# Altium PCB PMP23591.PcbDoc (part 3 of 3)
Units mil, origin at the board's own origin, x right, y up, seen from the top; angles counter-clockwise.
Board outline 3937.01 x 3937.01 mil, 6 copper layers (Top Layer, GND, Power Layer, Signal Layer, GND (Mid4), Bottom Layer), stack 66.824 mil thick; 197 components, 79 nets, 496 pads, 588 vias.
Unrouted connection lines stored in the file: 309.
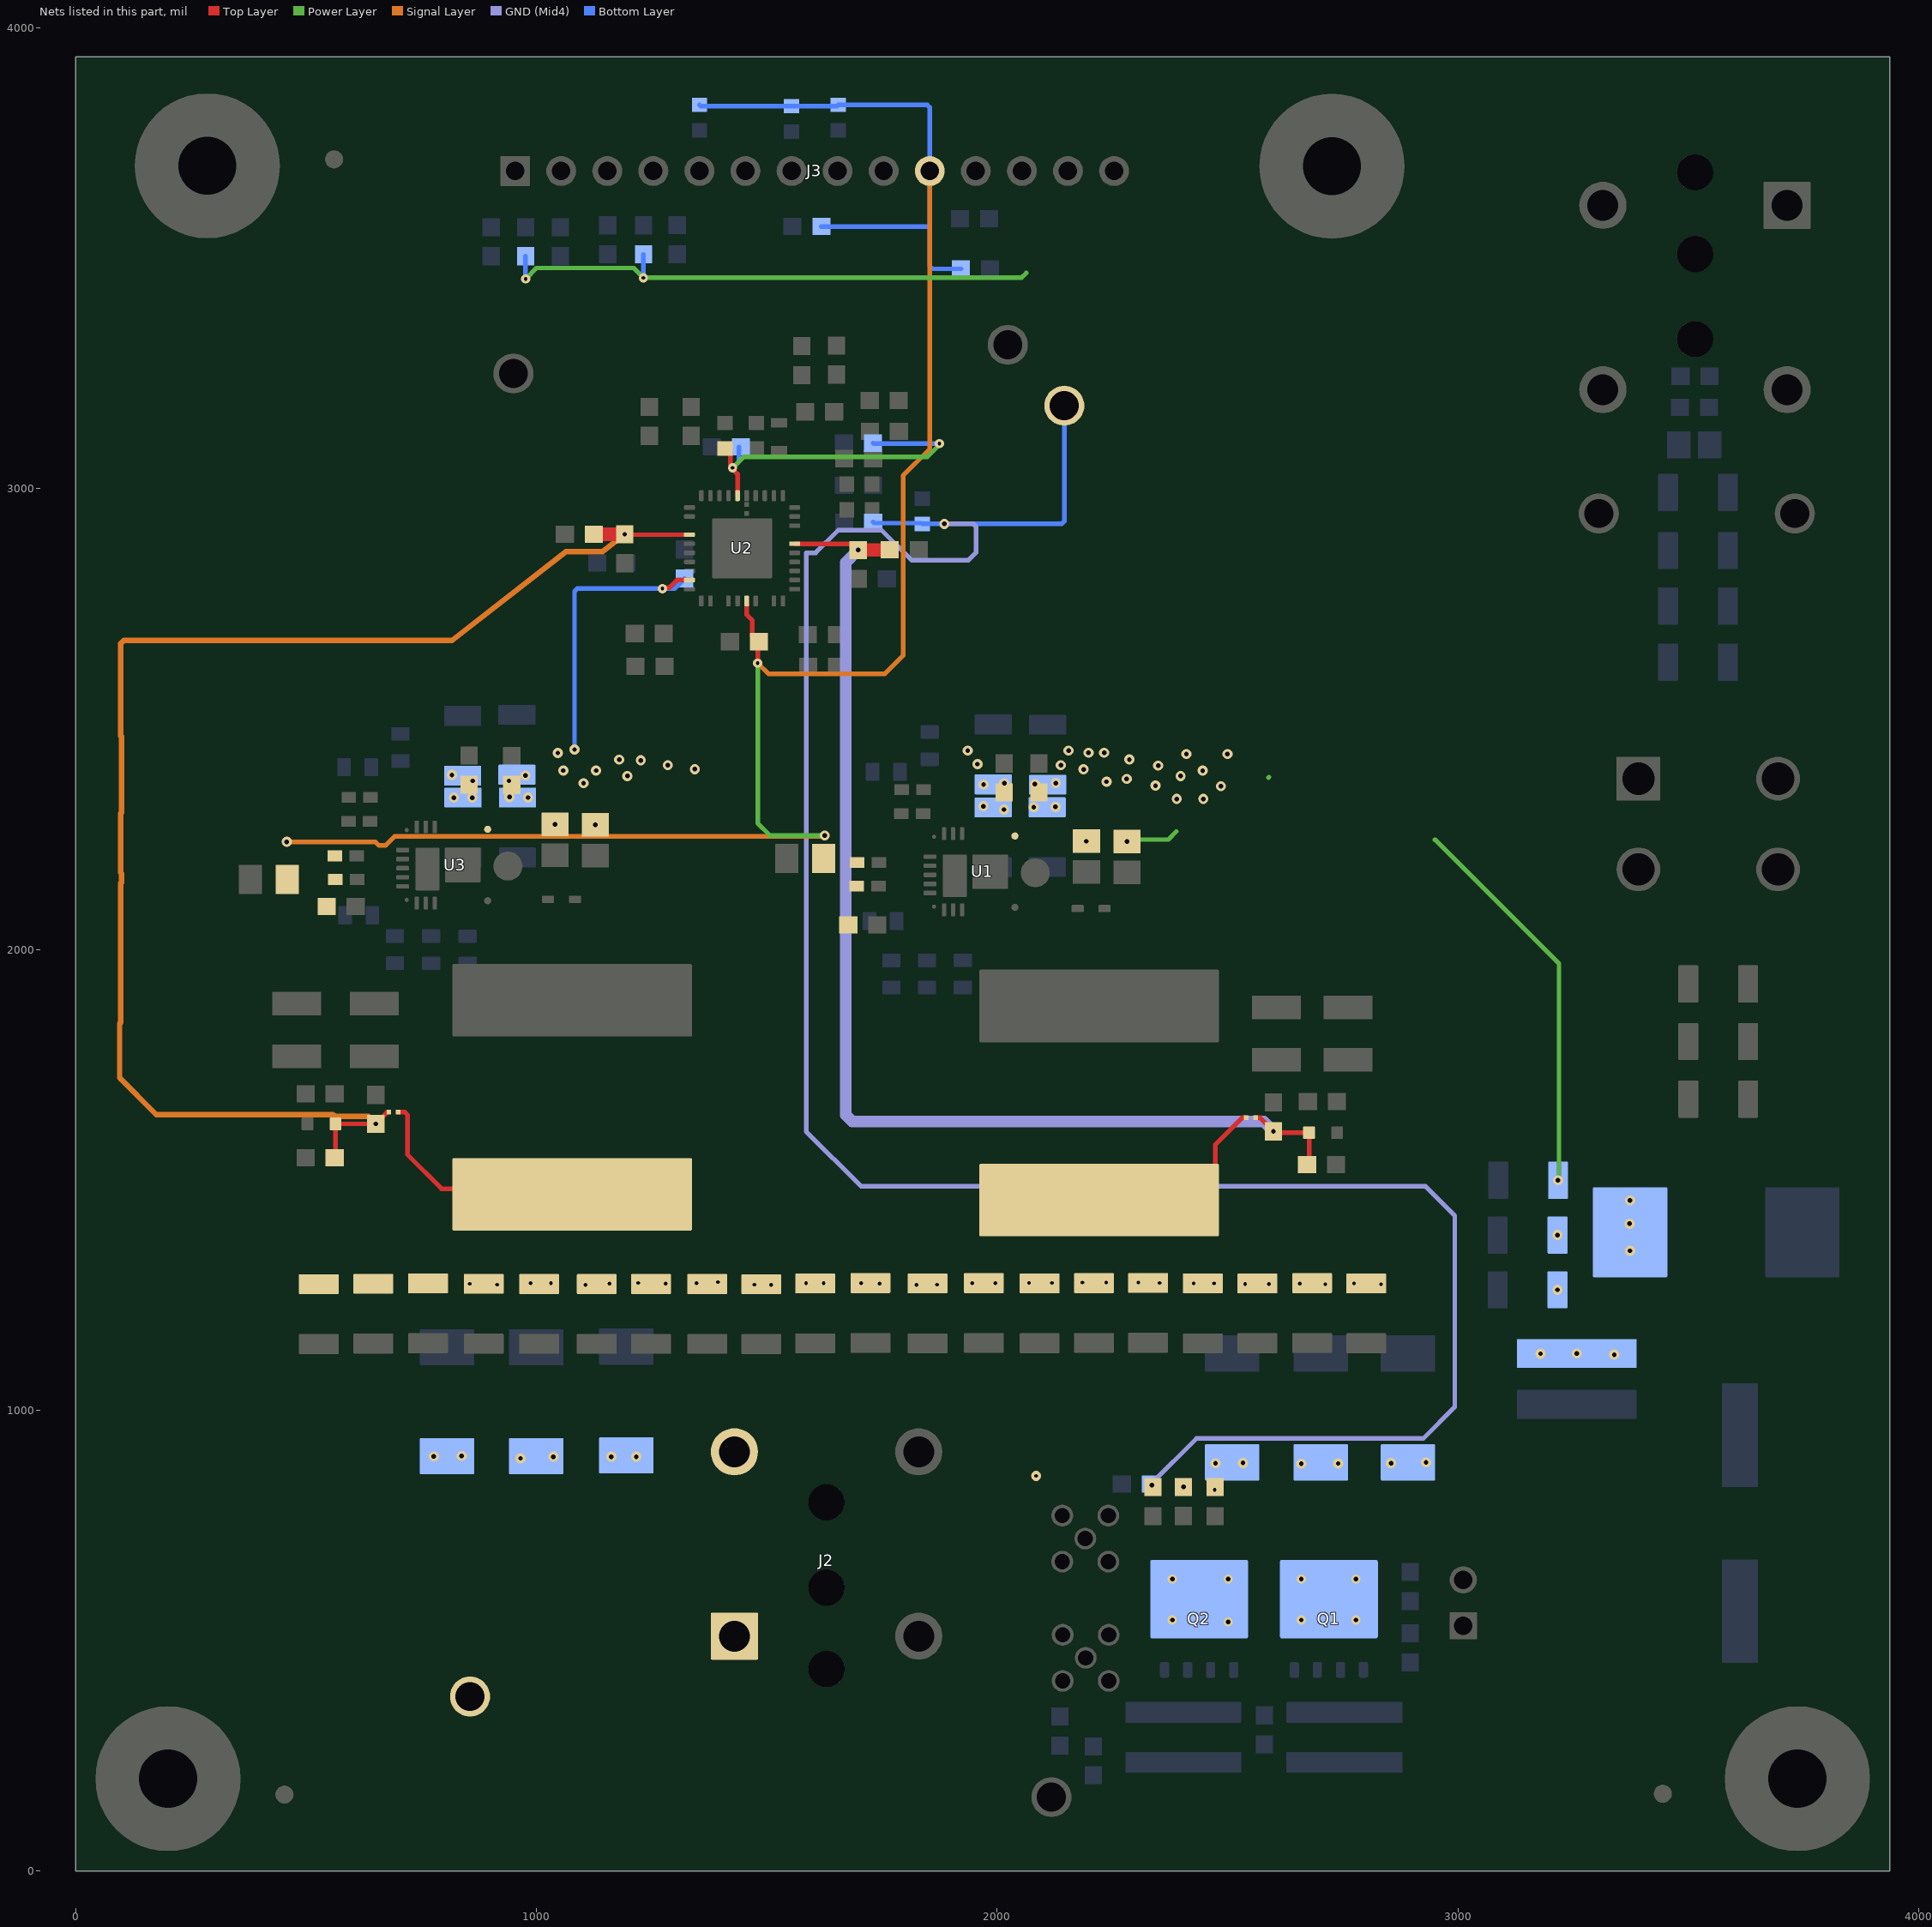
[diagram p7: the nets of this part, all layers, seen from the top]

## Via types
v1: diameter 22, hole 10, Top Layer to Bottom Layer, tented both sides, 256 vias
v2: diameter 20, hole 10, Top Layer to Bottom Layer, tented both sides, 193 vias
v3: diameter 22, hole 8, Top Layer to Bottom Layer, tented both sides, 59 vias
v4: diameter 20, hole 8, Top Layer to Bottom Layer, tented both sides, 56 vias
v5: diameter 19.68, hole 7.87, Top Layer to Bottom Layer, tented both sides, 18 vias
v6: diameter 230, hole 125, Top Layer to Bottom Layer, 4 vias
v7: diameter 24, hole 8, Top Layer to Bottom Layer, tented both sides, 2 vias

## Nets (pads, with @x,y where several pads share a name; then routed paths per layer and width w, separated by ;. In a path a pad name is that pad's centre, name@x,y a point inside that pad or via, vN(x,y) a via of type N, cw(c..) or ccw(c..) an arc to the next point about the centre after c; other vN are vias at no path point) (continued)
VCC: C22.1 C23.1 C40.1 C53.1 C54.1 J3.10 R2.1 R15.2 R21.1 R39.2 R41.2 R42.2 R43.2 R64.1 R65.1 U2.14 | length 4400.5
  Top Layer w10: U2.14@1456.05,2756.46 1456.05,2726.64 1468.17,2714.53 1468.17,2678.61 1480.01,2666.77 v4(1480.01,2621.39)
  Power Layer w10: v4(1480.01,2621.39) 1480.01,2274 1506.76,2247.26 v1(1625.53,2247.26)
  Signal Layer w10: v1(457.68,2233.61) 649.96,2233.61 658.03,2225.54 672.01,2225.54 692.1,2245.63 1623.9,2245.63 v1(1625.53,2247.26) ; v4(1480.01,2621.39) 1503.06,2598.34 1756.3,2598.34 1795.76,2637.8 1795.76,3028.58 1853.51,3086.34 J3.10@1853.51,3689.57
  Bottom Layer w10: R41.2@1353.76,3833.14 1356.57,3830.34 R42.2@1553.51,3830.34 1652.48,3830.34 R43.2@1655.28,3833.14 1847.66,3833.14 1853.51,3827.28 J3.10@1853.51,3689.57 1853.51,3568.98 ; R64.1@1618.31,3568.98 1853.51,3568.98 ; R65.1@1921.16,3477.23 1859.37,3477.23 1853.51,3483.09 1853.51,3568.98
VDDA: C41.2 R28.1 R46.2 U2.32 | length 782.3
  Top Layer w10: C41.2@1408.98,3087.48 1409.97,3087.48 1420.72,3076.74 1420.72,3052.78 1425.57,3047.92 v4(1425.57,3045.22) 1425.57,3042.51 1436.37,3031.71 U2.32@1436.37,2984.81
  Power Layer w10: v4(1425.57,3045.22) 1449.15,3068.79 1847.99,3068.79 1874.33,3095.13 v4(1874.33,3097.84)
  Bottom Layer w10: v4(1425.57,3045.22) 1439.55,3059.19 R28.1@1439.55,3090.75 ; R46.2@1730.43,3098.93 1731.72,3097.64 v4@1874.14,3097.64
VIN: C9.2 C10.2 C11.2 C18.2 C19.2 C20.2 C21.2 C24.2 C25.2 C26.1 C27.1 C39.1 C45.2 C46.2 C47.2 C48.2 C49.2 C50.2 C51.1 C52.1 L1.2 R1.2 R40.2 R60.2 U1.7 U2.8 U3.7 | length 2851.1
  Top Layer w10: v4(1273.19,2783.08) 1275.1,2784.99 1288.48,2784.99 1305.23,2801.74 U2.8@1332.04,2801.74
  Power Layer w10: v4(976.22,3455.2) 1000,3478.98 1146.6,3478.98 ; 1146.63,3479.01 1165.58,3479.01 1210.7,3478.98 v4(1231.9,3457.77) 2052.51,3457.77 2062.93,3468.19 ; 2269.63,2238.49 2371.23,2238.49 2388.77,2256.03 ; 2588.87,2372.93 2590.31,2374.37 ; 2950.23,2238.15 3219.3,1969.08 3219.3,1500.7 v1(3217.39,1498.79)
  Bottom Layer w10: v4(976.22,3455.2) R40.2@976.22,3504.77 ; v1(1082.55,2433.83) 1082.55,2777.22 1088.41,2783.08 v4(1273.19,2783.08) 1299.2,2783.08 1306.54,2790.41 1307.52,2790.41 1321.22,2804.11 C39.1@1321.22,2805.1 ; v4(1231.9,3457.77) 1231.9,3508.25 R60.2@1232.32,3508.66
  other v1: 3339.38,1120.39 3179.38,1122.5 3257.87,1122.97 3216.21,1261.25 3373.71,1345.83 3216.21,1380 3372.73,1404.74 3373.71,1455.17 2281.63,2234.15 2193.58,2234.77 1040.14,2271.36 1127.74,2270.51 2014.62,2303.64 2079.33,2308.59 2126.52,2309.42 1970.04,2310.85 2389.62,2326.6 2447.48,2326.6 820.58,2329.42 860.58,2329.42 981.48,2329.58 941.19,2330.68 2485.58,2354.29 2343.62,2355.49 1970.45,2357.94 2081.78,2358.7 1102.07,2360.78 2015.19,2360.78 2127.09,2361.07 2237.31,2364.05 861.21,2366 940.16,2365.99 2281.1,2370.18 1197.15,2376.45 2398.11,2376.45 975.91,2377.49 816.4,2378.74 1058.1,2388.24 1129.15,2388.24 2445.96,2388 1343.37,2391.34 2187.39,2390.88 2349.41,2398.98 1284.84,2399.98 2138.06,2399.98 1957.09,2402.16 1226.32,2410.35 1179.49,2411.88 2286.75,2412.31 2410.7,2424.09 2499.76,2424.09 1046.2,2426.33 2198.24,2426.75 2232.05,2426.75 1935.95,2431.66 2154.93,2431.66
Vout: C29.2 C30.2 C31.2 C32.2 C33.2 C34.2 C35.2 C36.2 C57.1 C58.2 C59.2 C60.2 C61.2 C62.2 C63.2 C64.2 C65.2 C66.2 C67.2 C72.2 C73.2 C74.2 C76.2 C79.2 C80.2 C81.2 C82.2 C83.2 C84.2 J2.1 L4.2 L6.2 NT1.2 NT2.2 Q1.5 Q1.6 Q1.7 Q1.8 Q1.9@2719.98,589.79 Q2.5 Q2.6 Q2.7 Q2.8 Q2.9@2438.28,589.69 R18.2 R37.2 R56.2 VOUT_BODE.1 VOUT_PWR1.1 | length 5920.5
  Top Layer w10: NT2.2@699.36,1646.64 714.14,1646.64 720,1640.78 720,1554.3 793.74,1480.56 L6.2@972.48,1480.56 ; L4.2@2221.16,1455.96 2399.9,1455.96 2473.64,1529.7 2473.64,1576.61 2531.71,1634.67 NT1.2@2540.58,1634.67
  GND (Mid4) w10: v1(1885.22,2923.63) 1948.01,2923.63 1953.87,2917.77 1953.87,2860.97 1937.88,2844.97 1813.92,2844.97 1748.97,2909.91 1654.89,2909.91 1605.77,2860.79 1585.36,2860.79 1585.36,1604.83 1704.12,1486.08 2929.22,1486.08 2993.24,1422.06 2993.24,1006.86 2924.83,938.45 2432.43,938.45 2335.53,841.55 2335.53,833.26 v2@2335.92,832.87
  Bottom Layer w10: R18.2@1730.69,2927.38 1732.75,2925.32 R37.2@1834.9,2925.32 ; R37.2@1836.84,2923.39 1837.08,2923.63 v1(1885.22,2923.63) 2139.72,2923.63 2145.57,2929.49 VOUT_BODE.1@2145.57,3180.17
  other v1: 2404.43,833.33 2660.11,883.81 2740.1,884.21 2473.78,884.58 2533.35,885.41 2854.79,885 2930.82,886.58 965.29,895.37 1036.58,898.95 1162.27,898.95 1216.49,898.95 777.03,899.67 837.45,900.59
  other v2: 2501.39,540.47 2380,544.45 2660,544.45 2778.89,544.45 2380,633.5 2501.39,633.5 2660,633.5 2778.89,633.5 2335.53,837.4
  other v3: 2472.16,827.06 2084.33,857.27 914.5,1272.42 1106.04,1271.9 1472.63,1272.42 1509.46,1271.9 1824.51,1271.9 1869.5,1272.42 2712.02,1273.4 2833.12,1273.4 854.74,1274.05 2538.07,1273.77 2589.52,1273.77 986.98,1275.45 1031.45,1275.45 1158.1,1274.86 1280.41,1274.86 1347.08,1275.32 1584.94,1275.32 1623.03,1275.32 1704.42,1275.32 1744.56,1274.86 2426.59,1274.94 2470.51,1274.94 2656.87,1274.74 2774.48,1274.94 1220.66,1276 1945.55,1275.73 1995.95,1275.73 2068.98,1276 2118.69,1276 2352.53,1276.1 2185.04,1276.97 2236.68,1276.97 2306.19,1277.17 1393.66,1278.08
VOUT1: C37.1 C43.1 C77.2 NT1.1 R9.2 R13.2 U2.23 | length 2590.3
  Top Layer w10: U2.23@1560.38,2880.48 1684.53,2880.48 v1(1698.06,2866.95) ; NT1.1@2560.58,1634.67 2570.95,1634.67 2599.45,1606.16 v1(2599.45,1605.18) ; C37.1@2602.45,1602.18 R9.2@2676.9,1602.18 2676.9,1537.33 R13.2@2672.63,1533.06
  Top Layer w30: v1(1698.06,2866.95) C77.2@1766.84,2867.84
  GND (Mid4) w25: v1(1698.06,2866.95) 1670.86,2839.75 1670.86,1782.86 1671.38,1782.34 1671.38,1756.35 1670.86,1755.83 1670.86,1640.82 1685.5,1626.18 2578.45,1626.18 v1(2599.45,1605.18)
VOUT2: C68.1 C69.1 C78.2 NT2.1 R33.2 R36.2 U2.3 | length 3127.7
  Top Layer w10: R36.2@561.72,1547.45 563.8,1549.53 R33.2@563.8,1621.33 v1(651.15,1621.3) ; v1(651.15,1621.3) 651.15,1622.28 675.5,1646.64 NT2.1@679.36,1646.64 ; v1(1191.39,2901.15) 1192.38,2900.16 U2.3@1332.04,2900.16
  Top Layer w30: C78.2@1124.6,2901.15 v1(1191.39,2901.15)
  Signal Layer w12: v1(651.15,1621.3) 634.89,1637.55 571.24,1637.55 566.29,1637.55 558.42,1641.5 174.8,1641.5 95,1721.3 95,1839.06 97.69,1841.75 97.69,2143.71 98.87,2144.9 98.87,2164.68 97.69,2165.87 97.69,2295.33 98.87,2296.51 98.87,2462.23 97.69,2463.41 97.69,2664.1 104.71,2671.13 817.09,2671.13 1063.56,2863.29 1138.7,2863.29 1142.72,2863.29 1146.08,2865.83 v1(1191.39,2901.15)
pads on no net: FID1.1 FID2.1 FID3.1 H1.1 H2.1 H3.1 H4.1 H5.0 H6.0 H7.0 H8.0 J1. J2. LBL1.0 Q1.9@2626.58,514.6 Q1.9@2667.62,526.21 Q1.9@2667.62,571.49 Q1.9@2667.62,616.76 Q1.9@2719.98,526.21 Q1.9@2719.98,571.49 Q1.9@2719.98,576.8 Q1.9@2719.98,616.76 Q1.9@2772.35,526.21 Q1.9@2772.35,571.49 Q1.9@2772.35,616.76 Q1.9@2813.39,514.6 Q2.9@2344.88,514.49 Q2.9@2385.92,526.11 Q2.9@2385.92,571.38 Q2.9@2385.92,616.66 Q2.9@2438.28,526.11 Q2.9@2438.28,571.38 Q2.9@2438.28,576.7 Q2.9@2438.28,616.66 Q2.9@2490.64,526.11 Q2.9@2490.64,571.38 Q2.9@2490.64,616.66 Q2.9@2531.69,514.49 U2.5

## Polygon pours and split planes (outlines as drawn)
NetC68_2 on Top Layer "TOP_LAYER_NETC68_2_P599" (solid, remove dead copper, pour order 599): 691.4,1822.76 691.31,1822.86 408.06,1822.86 408.06,1735.65 423.32,1720.38 527.34,1720.38 527.34,1651.34 715.48,1651.34 715.48,1822.44 715.43,1822.49
NetC37_2 on Top Layer "TOP_LAYER_NETC37_2_P598" (solid, remove dead copper, pour order 598): 2557.04,1807.43 2557.14,1807.53 2840.38,1807.53 2840.38,1720.32 2825.12,1705.06 2706.34,1705.06 2706.34,1636.01 2585.29,1636.01 2532.96,1688.34 2532.96,1807.11 2533.02,1807.17
AGND on Top Layer "TOP_LAYER_AGND" (solid, remove dead copper, pour order 600): 1240.55,2932.63 1159.84,2932.63 1159.84,3359.12 1180.72,3380 1906.22,3380 1906.22,2929.19 1710.71,2929.19 1710.71,3119.78 1705.53,3124.95 1240.55,3124.95
Vout on Top Layer "TOP_LAYER_VOUT_P590" (solid, remove dead copper, pour order 590): 613.53,1574.72 615.4,1572.84 2548.5,1572.84 2548.5,1542.28 2598.11,1492.67 2950.53,1492.67 2950.53,809.15 1760,809.15 1760,119.24 655.76,119.24 433.11,341.89 433.11,1314.89
VIN on Top Layer "TOP_LAYER_VIN_P603" (solid, remove dead copper, pour order 603): 415.12,2557.57 2560.58,2557.57 2560.58,2205.11 1940.94,2205.11 1940.94,2355.49 1943.71,2358.25 1943.71,2367.6 1772.47,2367.6 1772.47,2275.07 1769.51,2272.11 1777.65,2263.97 1837.86,2263.97 1837.86,2248.99 1838.63,2248.22 1835.02,2244.61 1797.4,2244.61 1797.4,2204.21 1796.49,2205.11 1717.6,2205.11 1717.6,2241.38 1583.39,2241.38 415.12,2241.38
NetL4_1 on Top Layer "TOP_LAYER_NETL4_1_P596" (solid, remove dead copper, pour order 596): 2510,1786.85 1954.09,1786.63 1954.09,2104.98 1961.61,2112.5 2146.13,2112.5 2198.24,2060.39 2510,2060.39
VCC on Top Layer "TOP_LAYER_VCC2_P270" (solid, remove dead copper, pour order 591): 415.12,2246.39 584.14,2246.39 584.14,2060.85 544.56,2060.85 434.99,2060.85 414.91,2080.93 414.91,2246.19
VCC on Top Layer "TOP_LAYER_VCC_P593" (solid, remove dead copper, pour order 593): 1584.94,2271.68 1715.57,2271.68 1715.57,2105.14 1715.57,2100.16 1714.59,2093.88 1714.59,2026.27 1605.02,2026.27 1584.94,2046.35
NetL6_1 on Top Layer "TOP_LAYER_NETL6_1_P595" (solid, remove dead copper, pour order 595): 1366.79,1807.33 810.32,1807.33 810.32,2135.62 904.54,2135.62 1058.1,2135.62 1058.1,2050.61 1366.79,2055.06
+Filter on Top Layer "TOP_LAYER_+FILTER_P601" (solid, remove dead copper, pour order 601): 3552.96,2241.38 3552.96,1250 3851.29,1250 3907.27,1250 3914.97,1257.7 3913.7,2241.38
PGND on Top Layer "TOP_LAYER_PGND_P604" (solid, remove dead copper, pour order 604): -43.69,7.99 3893.31,7.99 3893.31,2242.99 3028.16,2242.99 3028.16,3944.99 -43.69,3944.99
VIN on Power Layer "POWER_LAYER_VIN_P605" (solid, remove dead copper, pour order 605): 1944.42,2515.13 1942.22,2517.32 1868.99,2517.32 1868.99,2376.82 1882.88,2362.93 1943.71,2362.93 1943.71,2227.2 1962.92,2207.99 2602.44,2207.99 2602.44,1786.85 2886.3,1786.85 2888.45,1789.01 2888.45,1035 3683.79,1035 3683.79,1500.8 3427.7,1500.8 3427.7,2128.78 3122.59,2128.78 3039.33,2212.04 3004.5,2212.04 2968.75,2240.12 2950.23,2278.77 2950.23,3570.39 2043.87,3570.39 2043.87,2594.52 1944.42,2594.52
Vout on Power Layer "POWER_LAYER_VOUT_P606" (solid, remove dead copper, pour order 606): 205.04,1510 205.04,716.82 322.61,716.82 322.61,161.53 1760,161.53 1760,809.15 2290.12,809.15 2290.12,584.67 2809.25,584.67 2809.25,1510
PGND on Power Layer "POWER_LAYER_PGND_P615" (solid, remove dead copper, pour order 615): 20.05,17.74 3957.06,17.74 3957.06,2252.74 3050,2252.74 3050,3954.74 20.05,3954.74
NetC75_2 on Bottom Layer "BOTTOM_LAYER_NETC75_2_P608" (solid, remove dead copper, pour order 608): 2098.08,397.48 2138.2,397.61 2236.33,397.29 2236.33,466.54 2235.35,467.52 2248.25,480.41 2625.28,480.41 2769.3,480.41 2769.3,474.8 2774.91,480.41 2889.82,480.41 2889.82,245.94 2098.08,243.59
VIN on Bottom Layer "TOP_LAYER_VIN_P018" (solid, remove dead copper, pour order 613): 1102.63,2437.41 1102.07,2437.97 1102.07,2469.83 771.08,2469.83 771.08,2237.77 1367.98,2237.77 1367.98,2437.41
HS1 on Bottom Layer "BOTTOM_LAYER_HS1_P592" (solid, remove dead copper, pour order 592): 1873.2,2236.56 1872.67,2236.03 1721.09,2236.03 1721.09,2239.31 1669.1,2291.3 1669.1,2522.56 1900.35,2522.56 1889.88,2512.09 1889.88,2453.83 1876.19,2440.14 1758.7,2440.14 1758.7,2321.43 1781.86,2298.27 1873.17,2298.27 1873.17,2235.41 1873.22,2235.36
HS2 on Bottom Layer "BOTTOM_LAYER_HS2_P594" (solid, remove dead copper, pour order 594): 740.73,2499.61 740.66,2499.55 649.04,2499.55 561.72,2499.55 561.72,2322.76 616.42,2268.05 628.99,2268.05 638.7,2258.35 710.65,2258.35 710.65,2283.73 665.57,2328.81 624.53,2369.85 624.53,2418.04 634.64,2428.15 741.44,2428.15 741.44,2499.74 740.73,2500.45
NetC1_1 on Bottom Layer "BOTTOM_LAYER_NETC1_1_P597" (solid, remove dead copper, pour order 597): 3103.56,1071.59 3104.09,1071.06 3104.09,815.8 3683.79,815.8 3694.52,826.52 3694.52,1074.27 3106.25,1074.27 3103.65,1071.67
Vout on Bottom Layer "BOTTOM_LAYER_VOUT_P610" (solid, remove dead copper, pour order 610): 2991.7,488.74 2196.38,488.74 2196.38,790 1957.95,790 1370,790 1370,204.02 1345.98,180 715,180 715,1031.13 2991.7,1031.13
VIN on Bottom Layer "TOP_LAYER_VIN3_P079" (solid, remove dead copper, pour order 609): 3151.25,1602.33 3151.25,1600.12 3151.25,1598.75 3151.25,1201.31 3105.22,1201.31 3049.45,1145.54 3049.45,1083.39 3542.76,1083.39 3542.76,1602.33
AGND3 on Bottom Layer "BOTTOM_LAYER_AGND3_P611" (solid, remove dead copper, pour order 611): 330,2198.65 330,1920 337.73,1912.27 911.32,1912.27 911.32,1994.46 902.07,2003.71 619.52,2003.71 619.52,2116.9 616.42,2120 691.7,2120 691.7,2172.91 691.7,2180.93 690.7,2181.93 623.22,2181.93 620.72,2184.43 620.72,2198.65
AGND2 on Bottom Layer "BOTTOM_LAYER_AGND2_P612" (solid, remove dead copper, pour order 612): 1693.27,2150.5 1701.25,2150.23 1825.39,2150.23 1825.39,2095.75 1824.27,2094.64 1748.97,2094.64 1748.97,1937.1 1975,1937.1 1975,1870.72 1974.03,1869.75 1693.27,1869.75
PGND on Bottom Layer "BOTTOM_LAYER_PGND_P620" (solid, remove dead copper, pour order 620): 2.73,13.03 3939.73,13.03 3939.73,2248.03 3052.72,2248.03 3052.72,3950.03 2.73,3950.03
VIN on Bottom Layer "TOP_LAYER_VIN_P018" (solid, remove dead copper, pour order 614): 2586.17,2448.18 2586.17,2218.61 1904.25,2218.61 1904.25,2448.18
+Filter on Bottom Layer "BOTTOM_LAYER_+FILTER_P619" (solid, remove dead copper, pour order 619): 3555.13,2242.47 3555.13,1252.63 3915.87,1252.63 3915.87,2242.47
+Vin_Main on Bottom Layer "BOTTOM_LAYER_+VIN_MAIN_P618" (solid, remove dead copper, pour order 618): 3780,3680 3785,3675 3785,2885 3750,2850 3750,2315 3630.52,2315 3542.68,2402.84 3542.68,3002.32 3510,3035 3514.65,3039.65 3514.65,3544.65 3655,3685 3785,3685
GNDin on Bottom Layer "BOTTOM_LAYER_GNDIN_P616" (solid, remove dead copper, pour order 616): 3260,3677.5 3260,2893.36 3251.64,2885 3286.64,2850 3340,2850 3340,2315.1 3350,2305.1 3359.1,2314.21 3456.19,2314.21 3456.19,2364.55 3510,2418.36 3510,3520 3352.5,3677.5
PGND on GND "GND_PGND_P602" (solid, remove dead copper, pour order 602): 0,5 3937.01,5 3937.01,2240 3050,2240 3050,3942 0,3942
VIN on Signal Layer "SIGNAL_LAYER_VIN_P588" (solid, remove dead copper, pour order 588): 996.99,2281.54 996.99,2249.49 1331.15,2249.49 1332.04,2248.61 1336.67,2253.24 1336.67,2281.54 2110.87,2281.54 2181.76,2210.64 2861.22,2210.64 2861.22,2574.16 2826.22,2609.16 2803.77,2586.71 2342.63,2586.71 2342.63,2569.23 2243.62,2470.23 1384.86,2470.23 1236.67,2618.42 718.29,2618.42 718.29,2306.4 972.12,2306.4
Vout on Signal Layer "SIGNAL_LAYER_VOUT_P589" (solid, remove dead copper, pour order 589): 235.8,1470 235.8,716.82 664.24,716.82 664.24,145.71 1707.21,145.71 1707.21,809.15 2306.19,809.15 2306.19,613.5 2802.8,613.5 2802.8,1470
PGND on Signal Layer "SIGNAL_LAYER_PGND_P617" (solid, remove dead copper, pour order 617): 3.46,9 3940.47,9 3940.47,2244 3050,2244 3050,3946 3.46,3946
PGND on GND (Mid4) "GND_PGND_P607" (solid, remove dead copper, pour order 607): 0,5 3937.01,5 3937.01,2240 3050,2240 3050,3942 0,3942

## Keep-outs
Keep-Out Layer:
  text ".Layer_Name" at 577,-858.49 h30

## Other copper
Top Layer:
  pour cut-out: 705.1,1802.02 705.1,1584.13 1349.28,1584.13 1349.28,1802.02
  pour cut-out: 1951.53,1797.3 1951.53,1586.73 2569.03,1586.73 2569.96,1585.8 2569.96,1797.3
  pour cut-out: 1546.83,2779 1537.31,2779 1537.31,2962.26 1547.99,2962.26
  pour cut-out: 1345.19,2963.07 1345.19,2971.49 1441.05,2971.49 1441.05,2962.46
  pour cut-out: 1354.88,2779.33 1345.36,2779.33 1345.36,2963.07 1356.04,2963.07
  pour cut-out: 1451.92,2769.93 1451.92,2778.97 1546.9,2778.97 1546.9,2769.33
  pour cut-out: 1345.19,2769.75 1345.19,2778.97 1422.86,2778.97 1422.86,2769.26
  pour cut-out: 1470.86,2962.69 1470.86,2970.72 1548,2970.72 1548,2962.2
  text ".Layer_Name" at 577,-858.49 h30
Bottom Layer:
  text ".Layer_Name" at 577,-858.49 h30

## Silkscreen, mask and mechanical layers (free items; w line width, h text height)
Top Overlay:
  rectangle: 2980,160 3280,260
  lines w4: 1535.41,3477.07 1535.41,3620.19 ; 1635.35,3478.78 1635.35,3615.78
  lines w5: 900,3050 25,3050 25,2050 1025,2050 ; 2025,2050 3025,2050 3025,3050 2150,3050
  lines w10: 1101.51,2587.02 1102.07,2587.58
  text "PG1" at 1373,3547.09 h30 r90
  text "EN1" at 1069.97,3545.44 h30 r90
  text "EN2" at 1166.9,3545.44 h30 r90
  text "VCC" at 1869.18,3531 h30 r90
  text "PGND" at 966.59,3512.52 h30 r90
  text "PGND" at 1271.05,3510.02 h30 r90
  text "IMON1" at 2167.98,3499.49 h30 r90
  text "IMON2" at 2269.26,3493.73 h30 r90
  text "FAULT1" at 1571.7,3478.18 h30 r90
  text "FAULT2" at 1672.49,3478.18 h30 r90
  text "TIMESENSE2" at 1456.05,3446.44 h30 r90
  text "SYNCOUT" at 1773.03,3443.87 h30 r90
  text "PFM/SYNC" at 1968.33,3440 h30 r90
  text "TIMESENSE1" at 2062.93,3439.18 h30 r90
  text "Heatsink outline" at 2509.06,3002.79 h30
  text "Heatsink outline 3 inches by 1 inch" at 93.33,2973.63 h30
  text "Thermal pad required" at 342.01,2906.47 h30
  text "20V to 60V" at 3574.97,2800.33 h30
  text "'.PRJ_Number'.PCB_Rev" at 3125,2333.58 h30 r90
  text "Heatsink mounts w/ 4-40 screws" at 2652.18,2081.43 h30 r90
  text "Heatsink mounts w/ 4-40 screws" at 149.67,2063.42 h30 r90
  text "Signal generator for dynamic load" at 2804.02,705.09 h30
  text "PGND" at 3083.69,631.28 h30
  text "V_Sense" at 2117.97,602.28 h30
  text "I_Sense" at 2124.37,339.79 h30
  text "Rev..PCB_Rev-" at 3021.7,293.25 h30
  text "50A max" at 789.28,254.28 h30
  text ".Layer_Name" at 577,-858.49 h30
Bottom Overlay:
  text ".Layer_Name" at 577,-858.49 h30
Top Paste:
  text ".Layer_Name" at 577,-858.49 h30
Bottom Paste:
  text ".Layer_Name" at 577,-858.49 h30
Top Solder:
  text ".Layer_Name" at 577,-858.49 h30
  text ".Layer_Name" at 577,-858.49 h30
Bottom Solder:
  text ".Layer_Name" at 577,-858.49 h30
Drill Guide:
  text ".Layer_Name" at 577,-858.49 h30
M1 Board Outline:
  the board outline again, w10
  text ".Layer_Name" at 577,-858.49 h30
M2 Board Dimensions:
  rectangle: 0,-275 125,-150
  rectangle: 125,-400 500,-275
  lines w7: 0,-275 1000,-275 ; 125,-400 125,-150 ; 250,-400 250,-150 ; 500,-400 500,-150 ; 750,-400 750,-150 ; 0,-400 1000,-400 1000,-150 0,-150 0,-400
  text ".Layer_Name" at 577,-858.49 h30
M3 3D STEP Top:
  text ".Layer_Name" at 577,-858.49 h30
M4 3D STEP Bottom:
  text ".Layer_Name" at 577,-858.49 h30
M5 Assembly Top:
  lines w10: -292,-930.17 6308,-930.17 ; -292,-726.83 6310,-726.83 ; -292,-523.5 -292,-1133.5 3713,-1133.5 6310,-1133.5 6310,-523.5 -291.5,-523.5 -291.5,-1133.5 1284,-1133.5 ; 2173,-1133.5 2173,-523.5 ; 3440,-726.83 3440,-523.5 ; 4280,-726.83 4280,-523.5 ; 4902,-1140 4902,-937.17
  text "COMPONENTS MARKED 'DNP' SHOULD NOT BE POPULATED." at 1153.5,-318.5 h30
  text "ASSEMBLY VARIANT:" at 1153,-434 h30
  text ".VariantName" at 2189,-434 h30
  text "PCB VIEWED FROM TOP SIDE" at -228.5,-655.67 h30
  text "BOARD #:" at 2248,-655.67 h30
  text ".PRJ_Number" at 2793.5,-655.67 h30
  text "REV:" at 3638,-655.67 h30
  text ".PCB_Rev" at 3929.5,-655.67 h30
  text "SVN REV:" at 4476,-655.67 h30
  text ".VersionControl_RevNumber" at 4982,-655.67 h30
  text "TID #:" at 2248,-859 h30
  text ".TID" at 2793.5,-859 h30
  text "PLOT NAME =" at -228.5,-1064.34 h30
  text ".plot_File_Name" at 577,-1064.34 h30
  text "GENERATED    :" at 2250,-1064.34 h30
  text ".Print_Date" at 3119.5,-1064.34 h30
  text ".Print_Time" at 3848.5,-1064.34 h30
  text "TEXAS INSTRUMENTS" at 5113,-1064.34 h30
M6 Assembly Bottom:
  lines w10: -292.5,-727.33 6309.5,-727.33 ; -290.5,-930.67 6309.5,-930.67 ; 1115.5,-1140.5 1115.5,-937.67 ; 1737.5,-727.33 1737.5,-524 ; 2577.5,-727.33 2577.5,-524 ; 3844.5,-1134 3844.5,-524 ; 4733.5,-1134 6309,-1134 6309,-524 -292.5,-524 -292.5,-1134 2304.5,-1134 6309.5,-1134 6309.5,-524
  text "COMPONENTS MARKED 'DNP' SHOULD NOT BE POPULATED." at 6102,-318 h30
  text ".VariantName" at 5058,-434 h30
  text "ASSEMBLY VARIANT:" at 6097,-434 h30
  text ".VersionControl_RevNumber" at 1035.5,-656.17 h30
  text "SVN REV:" at 1541.5,-656.17 h30
  text ".PCB_Rev" at 2088,-656.17 h30
  text "REV:" at 2379.5,-656.17 h30
  text ".PRJ_Number" at 3224,-656.17 h30
  text "BOARD #:" at 3769.5,-656.17 h30
  text "PCB VIEWED FROM BOTTOM SIDE" at 6246,-656.17 h30
  text ".TID" at 3224,-859.5 h30
  text "TID #:" at 3769.5,-859.5 h30
  text "TEXAS INSTRUMENTS" at 904.5,-1064.84 h30
  text ".Print_Time" at 2169,-1064.84 h30
  text ".Print_Date" at 2898,-1064.84 h30
  text "GENERATED    :" at 3767.5,-1064.84 h30
  text ".plot_File_Name" at 5440.5,-1064.84 h30
  text "PLOT NAME =" at 6246,-1064.84 h30
M9 Title Sheet:
  drawing of 57 lines, arcs and shapes, not listed
  text "1" at 739.84,8036.5 h30
  text "2" at 3235.5,8036.5 h30
  text "3" at 5724.84,8036.5 h30
  text "4" at 8231.51,8036.5 h30
  text "5" at 10730.5,8036.5 h30
  text "6" at 13235.5,8036.5 h30
  text "A" at -416.5,6893.5 h30
  text "A" at 14383.5,6893.5 h30
  text "B" at -416.5,4513.5 h30
  text "B" at 14383.5,4513.5 h30
  text "C" at -416.5,2138.5 h30
  text "C" at 14383.5,2138.5 h30
  text "PROJECT TITLE:" at 11343.5,277.5 h30
  text ".PRJ_Title" at 11393.5,144.17 h30
  text "DESIGNED FOR:" at 11343.5,-23.5 h30
  text ".PRJ_Customer" at 11393.5,-163.5 h30
  text "D" at -416.5,-231.5 h30
  text "D" at 14383.5,-231.5 h30
  text "FILE NAME:" at 11343.5,-323.5 h30
  text ".PCB_File_Name_No_Path" at 11393.5,-443.5 h30
  text "Texas Instruments (TI) and/or its licensors do not warrant the accuracy or completeness of this specification" at 6374,-605.34 h30
  text "ENGINEER:" at 11343.5,-613.5 h30
  text "LAYOUT BY:" at 12848.5,-613.5 h30
  text "or any information contained therein. TI and/or its licensors do not warrant that this design will meet" at 6329.01,-718 h30
  text ".PRJ_Engineer" at 11393.5,-768.49 h30
  text ".PCB_Layout" at 12899,-768.49 h30
  text "the specifications, will be suitable for your application or fit for any particular purpose, or will operate in" at 6329.01,-830.67 h30
  text ".Layer_Name" at 577,-858.49 h30
  text "ALTIUM DESIGNER VERSION:" at 12848.5,-923.5 h30
  text "an implementation. TI and/or its licensors do not warrant that the design is production worthy. You should" at 6329.01,-943.33 h30
  text "completely validate and test your design implementation to confirm the system functionality for your application." at 6374,-1056 h30
  text ".print_Scale" at 11393.5,-1056.83 h30
  text ".Application_BuildNumber" at 12899,-1056.83 h30
  text "1" at 739.84,-1263.5 h30
  text "2" at 3235.5,-1263.5 h30
  text "3" at 5724.84,-1263.5 h30
  text "4" at 8231.51,-1263.5 h30
  text "5" at 10730.5,-1263.5 h30
  text "6" at 13235.5,-1263.5 h30
M10 Fab Notes:
  drawing of 189 lines, arcs and shapes, not listed
  text "DESIGN INFORMATION" at 12382.02,6356.17 h30
  text "MIN. TRACK WIDTH:" at 11737.46,6224.05 h30
  text "8" at 12833.7,6224.05 h30
  text "MIL" at 12988.46,6224.05 h30
  text "7.874" at 12667.32,6102.36 h30
  text "MIN. CLEARANCE:" at 11737.46,6099.92 h30
  text "MIL" at 12988.46,6099.92 h30
  text "MIN. VIA PAD SIZE:" at 11737.46,5975.8 h30
  text "24" at 12803.71,5975.8 h30
  text "MIL" at 12988.46,5975.8 h30
  text "0.05mm (2MIL)" at 12432.46,5845.9 h30
  text "MINIMUM ANNULAR RING" at 11408.23,5837.67 h30
  text "EXTERNAL" at 13140.46,5837.67 h30
  text "PER" at 11608.23,5727.55 h30
  text "IPC-D-275 CLASS 2 LEVEL C" at 11828.23,5727.54 h30
  text "MIL, HOLES" at 13316.46,5627.07 h30
  text "+/-" at 12924,5618.48 h30
  text "+/-" at 13778,5618.48 h30
  text "REGISTRATION TOLERANCES:" at 11408.23,5617.42 h30
  text "METAL" at 12608,5617.42 h30
  text "5" at 13184.2,5617.42 h30
  text "3" at 14017.2,5617.42 h30
  text "MIL" at 14133.46,5617.42 h30
  text "HOLE SIZE TOLERANCE (UNLESS OTHERWISE SPECIFIED):" at 11408.23,5519.1 h30
  text "+/-" at 13778,5516.23 h30
  text "3" at 14017.2,5515.17 h30
  text "MIL" at 14133.46,5515.17 h30
  text "MATERIAL:" at 11333.46,5377.52 h30
  text "FR-4 High Tg" at 12319.9,5249 h30
  text "X" at 12175.46,5241.01 h30
  text "FR-4" at 11754.46,5236.49 h30
  text "OTHER" at 13242.46,5236.49 h30
  text "62 MIL (1.6mm) +/-10%" at 12074.56,5093.46 h30
  text "X" at 11954.46,5091.01 h30
  text "THICKNESS:" at 11408.23,5085.24 h30
  text "OTHER" at 13359.46,5085.24 h30
  text "TOLERANCE:" at 11408.23,4946.92 h30
  text "X" at 12256.46,4946.92 h30
  text "ANSI IPC-6012 TYPE 3 CLASS 2" at 12434.48,4946.92 h30
  text "OTHER +/-" at 12434.46,4802.73 h30
  text "BOW & TWIST:" at 11408.23,4657.54 h30
  text "X" at 12256.46,4657.54 h30
  text "ANSI IPC-6012 TYPE 3 CLASS 2" at 12434.48,4657.54 h30
  text "OTHER +/-" at 12434.46,4510.85 h30
  text "DRILLING:" at 11333.46,4380.23 h30
  text "NC_DRILL FILES" at 13094.46,4275.04 h30
  text "REFERENCE:" at 11408.23,4271.1 h30
  text "X" at 12065.46,4271.01 h30
  text "AS SHOWN" at 12243.46,4271.1 h30
  text "X" at 12966.46,4271.1 h30
  text "OTHER" at 13392.46,4128.85 h30
  text "PTH COPPER THICKNESS:" at 11407.91,4125.32 h30
  text "X" at 12547.14,4125.32 h30
  text "20-30 um" at 12675.14,4125.32 h30
  text "BOARD FINISH:" at 11333.46,3977.73 h30
  text "SILKSCREEN:" at 11488.68,3867.6 h30
  text "X" at 12446.46,3867.6 h30
  text "TOP" at 12563.46,3867.6 h30
  text "X" at 12956.46,3867.6 h30
  text "BOTTOM" at 13074.46,3867.6 h30
  text "SILKSCREEN COLOR:" at 11488.68,3712.41 h30
  text "X" at 12445.46,3712.41 h30
  text "WHITE" at 12563.46,3712.41 h30
  text "OTHER" at 13074.46,3712.41 h30
  text "X" at 12576.46,3568.96 h30
  text "GREEN" at 12694.46,3568.96 h30
  text "OTHER" at 13312.46,3568.96 h30
  text "SOLDER RESIST COLOR:" at 11488.68,3562.1 h30
  text "X" at 12576.46,3414.71 h30
  text "MATTE" at 12694.46,3414.71 h30
  text "SEMI-GLOSS" at 13312,3414.07 h30
  text "IMMERSION GOLD (ENIG)" at 12394.46,3241.94 h30
  text "ENEPIG" at 13732,3234.72 h30
  text "SURFACE FINISH:" at 11333.46,3233.72 h30
  text "X" at 12216.46,3233.72 h30
  text "IMM. TIN/SILVER OR EQUIV" at 11663,3096.4 h30
  text "OTHER" at 13094.46,3092.47 h30
  text "ARRAY/PANEL:" at 11333.46,2937.09 h30
  text "CUT AND TRIM PER M1 BOARD OUTLINE" at 12394.46,2928.87 h30
  text "N.C. ROUTE" at 12394.46,2792.9 h30
  text "X" at 13082.46,2792.9 h30
  text "V. SCORE" at 13260.46,2792.9 h30
  text "CERTIFICATION:" at 11333.46,2663.77 h30
  text "MATERIALS AND WORKMANSHIP FOR ALL PCBS" at 12058.46,2663.77 h30
  text "TO MEET OR EXCEED THE REQUIREMENTS OF:" at 12058.46,2569.71 h30
  text "X" at 11695.97,2441.08 h30
  text "ANSI IPC-A-600F CLASS ->" at 11823.96,2441.08 h30
  text "X" at 13471.97,2441.08 h30
  text "2" at 13581.96,2441.08 h30
  text "1" at 13266.96,2439.58 h30
  text "3" at 13935.96,2439.58 h30
  text ".PRJ_Number" at 2987.94,2377.46 h30 r90
  text "X" at 12507.97,2293.39 h30
  text "RoHS" at 12635.96,2293.39 h30
  text "OTHER" at 13280.36,2293.39 h30
  text "PER ORDER" at 13677.42,2293.39 h30
  text "ALL BOARDS MUST MEET OR EXCEED UL94-V0 REQUIREMENTS." at 11361,2139.57 h30
  text "PCB MUST BEAR THE UL94V-0 UL REGISTERED MATERIAL ID NUMBER" at 11361,2023.5 h30
  text "ADDITIONAL REQUIREMENTS:" at 11333.46,1854.08 h30
  text "MICROSECTION:" at 11408.23,1746.95 h30
  text "YES" at 12313.96,1746.95 h30
  text ".PRJ_Title" at 4320,1715 h30
  text "REQUIRED" at 13175.46,1602.62 h30
  text "BARE BOARD ELEC. TEST:" at 11408.23,1599.76 h30
  text "NONE" at 12713.96,1599.76 h30
  text "X" at 13057.46,1599.76 h30
  text "PER ORDER" at 13767.46,1599.76 h30
  text "XX MIL VIAS REQUIRE NON-CONDUCTIVE FILL AND PLANARIZE" at 11576.38,1394.82 h30
  text "XX MIL VIAS REQUIRE CONDUCTIVE FILL AND PLANARIZE" at 11584.38,1290.84 h30
  text "OUTER XX MIL TRACES REQUIRE 50 OHM SINGLE-ENDED IMPEDANCE" at 11583.39,1127.46 h30
  text "LAYER 2 & 3 (INNER LAYERS) XX MIL WIDE, XX MIL SPACE / TRACES REQUIRE 100 OHM DIFFERENTIAL IMPEDANCE" at 11575.39,891.74 h30
  text ".Layer_Name" at 577,-858.49 h30
M11 Gerber Information:
  lines w10: -292,-930.17 6308,-930.17 ; -292,-726.83 6310,-726.83 ; -292,-523.5 -292,-1133.5 3713,-1133.5 6310,-1133.5 6310,-523.5 -291.5,-523.5 -291.5,-1133.5 1284,-1133.5 ; 2173,-1133.5 2173,-523.5 ; 3440,-726.83 3440,-523.5 ; 4280,-726.83 4280,-523.5 ; 4902,-1140 4902,-937.17
  text "ALL ARTWORK VIEWED FROM TOP SIDE" at -228.5,-655.67 h30
  text "BOARD #:" at 2248,-655.67 h30
  text ".PRJ_Number" at 2793.5,-655.67 h30
  text "REV:" at 3638,-655.67 h30
  text ".PCB_Rev" at 3929.5,-655.67 h30
  text "SVN REV:" at 4476,-655.67 h30
  text ".VersionControl_RevNumber" at 4982,-655.67 h30
  text "LAYER NAME =" at -228.5,-858.49 h30
  text "TID #:" at 2248,-859 h30
  text ".TID" at 2793.5,-859 h30
  text "PLOT NAME =" at -228.5,-1064.34 h30
  text ".plot_File_Name" at 577,-1064.34 h30
  text "GENERATED    :" at 2250,-1064.34 h30
  text ".Print_Date" at 3119.5,-1064.34 h30
  text ".Print_Time" at 3848.5,-1064.34 h30
  text "TEXAS INSTRUMENTS" at 5113,-1064.34 h30
M12 Stackup:
  drawing of 264 lines, arcs and shapes, not listed
  text "Layer" at 6020.23,7421.05 h60
  text "Name" at 6271.32,7421.05 h60
  text "Material" at 6756.9,7421.05 h60
  text "Thickness" at 7193.25,7421.05 h60
  text "Constant" at 7551.68,7421.05 h60
  text "Board Layer Stack" at 7883.41,7421.05 h60
  text "Top Overlay" at 6271.32,7301.05 h60
  text "Top Solder" at 6271.32,7181.05 h60
  text "Solder Resist" at 6756.9,7181.05 h60
  text "0.50mil" at 7193.25,7181.05 h60
  text "3.5" at 7551.68,7181.05 h60
  text "1" at 6020.23,7061.05 h60
  text "Top Layer" at 6271.32,7061.05 h60
  text "2.80mil" at 7193.19,7061.05 h60
  text "Dielectric 1" at 6271.32,6941.05 h60
  text "FR-4 High Tg" at 6756.9,6941.05 h60
  text "7.00mil" at 7193.25,6941.05 h60
  text "4.2" at 7551.68,6941.05 h60
  text "2" at 6020.17,6821.05 h60
  text "GND" at 6271.32,6821.05 h60
  text "2.76mil" at 7193.19,6821.05 h60
  text "Dielectric 2" at 6271.32,6701.05 h60
  text "FR-4 High Tg" at 6756.9,6701.05 h60
  text "14.00mil" at 7193.25,6701.05 h60
  text "4.2" at 7551.68,6701.05 h60
  text "3" at 6020.23,6581.05 h60
  text "Power Layer" at 6271.32,6581.05 h60
  text "2.76mil" at 7193.19,6581.05 h60
  text "Dielectric 4" at 6271.32,6461.05 h60
  text "FR-4 High Tg" at 6756.9,6461.05 h60
  text "8.20mil" at 7193.25,6461.05 h60
  text "4.2" at 7551.68,6461.05 h60
  text "4" at 6020.23,6341.05 h60
  text "Signal Layer" at 6271.32,6341.05 h60
  text "2.76mil" at 7193.19,6341.05 h60
  text "Dielectric 5" at 6271.32,6221.05 h60
  text "FR-4 High Tg" at 6756.9,6221.05 h60
  text "14.00mil" at 7193.25,6221.05 h60
  text "4.2" at 7551.68,6221.05 h60
  text "5" at 6020.23,6101.05 h60
  text "GND" at 6271.32,6101.05 h60
  text "2.76mil" at 7193.19,6101.05 h60
  text "Dielectric 3" at 6271.32,5981.05 h60
  text "FR-4 High Tg" at 6756.9,5981.05 h60
  text "7.00mil" at 7193.25,5981.05 h60
  text "4.2" at 7551.68,5981.05 h60
  text "6" at 6020.23,5861.05 h60
  text "Bottom Layer" at 6271.32,5861.05 h60
  text "2.80mil" at 7193.19,5861.05 h60
  text "Bottom Solder" at 6271.32,5741.05 h60
  text "Solder Resist" at 6756.9,5741.05 h60
  text "0.50mil" at 7193.25,5741.05 h60
  text "3.5" at 7551.68,5741.05 h60
  text "Bottom Overlay" at 6271.32,5621.05 h60
  text ".Layer_Name" at 577,-858.49 h30
M13 Component Bodies Top:
  text ".Layer_Name" at 577,-858.49 h30
M14 Component Bodies Bottom:
  text ".Layer_Name" at 577,-858.49 h30
M15 Courtyards Top:
  text ".Layer_Name" at 577,-858.49 h30
M16 Courtyards Bottom:
  text ".Layer_Name" at 577,-858.49 h30
Drill Drawing:
  circle w10: c4699.83,3161.36 r16.58
  circle w10: c4699.83,3161.36 r27.63
  circle w10: c4699.83,2291.12 r27.63
  lines w10: 4672.2,2443.07 4727.45,2443.07 4699.83,2387.82 4672.2,2443.07 ; 4672.2,2525.95 4686.01,2525.95 4699.83,2512.14 4713.64,2525.95 4727.45,2525.95 4713.64,2539.76 4727.45,2553.58 4713.64,2553.58 4699.83,2567.39 4686.01,2553.58 4672.2,2553.58 4686.01,2539.76 4672.2,2525.95 ; 4672.2,2691.71 4727.45,2691.71 4699.83,2636.46 4672.2,2691.71 ; 4672.2,2760.78 4727.45,2760.78 4727.45,2816.03 4672.2,2816.03 4672.2,2760.78 ; 4672.2,2898.91 4686.01,2898.91 4699.83,2885.1 4713.64,2898.91 4727.45,2898.91 4713.64,2912.72 4727.45,2926.54 4713.64,2926.54 4699.83,2940.35 4686.01,2926.54 4672.2,2926.54 4686.01,2912.72 4672.2,2898.91 ; 4672.2,3009.42 4699.83,3023.23 4727.45,3009.42 4713.64,3037.04 4727.45,3064.67 4699.83,3050.86 4672.2,3064.67 4686.01,3037.04 4672.2,3009.42 ; 4672.2,3285.68 4699.83,3258.06 4727.45,3285.68 4699.83,3313.31 4672.2,3285.68 ; 4672.2,3382.38 4672.2,3396.19 4686.01,3410 4672.2,3423.82 4672.2,3437.63 4686.01,3437.63 4699.83,3423.82 4713.64,3437.63 4727.45,3437.63 4727.45,3423.82 4713.64,3410 4727.45,3396.19 4727.45,3382.38 4713.64,3382.38 4699.83,3396.19 4686.01,3382.38 4672.2,3382.38 ; 4672.2,3520.51 4686.01,3520.51 4686.01,3506.7 4713.64,3506.7 4713.64,3520.51 4727.45,3520.51 4727.45,3548.14 4713.64,3548.14 4713.64,3561.95 4686.01,3561.95 4686.01,3548.14 4672.2,3548.14 4672.2,3520.51 ; 4672.2,3631.02 4727.45,3631.02 4727.45,3686.27 4672.2,3686.27 4672.2,3631.02 ; 4683.25,2432.02 4716.4,2432.02 4699.83,2398.87 4683.25,2432.02 ; 4683.25,2531.48 4691.54,2531.48 4699.83,2523.19 4708.12,2531.48 4716.4,2531.48 4708.12,2539.76 4716.4,2548.05 4708.12,2548.05 4699.83,2556.34 4691.54,2548.05 4683.25,2548.05 4691.54,2539.76 4683.25,2531.48 ; 4683.25,3642.07 4716.4,3642.07 4716.4,3675.22 4683.25,3675.22 4683.25,3642.07
  lines w12: 4622.11,2226.2 7853.6,2226.2 ; 4622.11,3718.04 7853.6,3718.04 ; 4959.97,2101.88 4959.97,3842.36 ; 5291.97,2101.88 5291.97,3842.36 ; 5928.54,2101.88 5928.54,3842.36 ; 6187.68,2101.88 6187.68,3842.36 ; 6562.83,2101.88 6562.83,3842.36 ; 7287.17,2101.88 7287.17,3842.36 ; 4622.11,2101.88 7853.6,2101.88 7853.6,3842.36 4622.11,3842.36 4622.11,2101.88
  text "Symbol" at 4696.7,3755.34 h72
  text "Quantity" at 4997.27,3755.34 h72
  text "Finished Hole Size" at 5329.27,3755.34 h72
  text "Plated" at 5965.83,3755.34 h72
  text "Hole Type" at 6224.97,3755.34 h72
  text "Drill Layer Pair" at 6600.13,3755.34 h72
  text "Hole Tolerance" at 7324.46,3755.34 h72
  text "6" at 4997.27,3631.02 h60
  text "78.74mil (2.000mm)" at 5329.27,3631.02 h60
  text "NPTH" at 5965.83,3631.02 h60
  text "Round" at 6224.97,3631.02 h60
  text "Top Layer - Bottom Layer" at 6600.13,3631.02 h60
  text "18" at 4997.27,3506.7 h60
  text "7.87mil (0.200mm)" at 5329.27,3506.7 h60
  text "PTH" at 5965.83,3506.7 h60
  text "Round" at 6224.97,3506.7 h60
  text "Top Layer - Bottom Layer" at 6600.13,3506.7 h60
  text "117" at 4997.27,3382.38 h60
  text "8.00mil (0.203mm)" at 5329.27,3382.38 h60
  text "PTH" at 5965.83,3382.38 h60
  text "Round" at 6224.97,3382.38 h60
  text "Top Layer - Bottom Layer" at 6600.13,3382.38 h60
  text "449" at 4997.27,3258.06 h60
  text "10.00mil (0.254mm)" at 5329.27,3258.06 h60
  text "PTH" at 5965.83,3258.06 h60
  text "Round" at 6224.97,3258.06 h60
  text "Top Layer - Bottom Layer" at 6600.13,3258.06 h60
  text "10" at 4997.27,3133.74 h60
  text "33.07mil (0.840mm)" at 5329.27,3133.74 h60
  text "PTH" at 5965.83,3133.74 h60
  text "Round" at 6224.97,3133.74 h60
  text "Top Layer - Bottom Layer" at 6600.13,3133.74 h60
  text "14" at 4997.27,3009.42 h60
  text "40.00mil (1.016mm)" at 5329.27,3009.42 h60
  text "PTH" at 5965.83,3009.42 h60
  text "Round" at 6224.97,3009.42 h60
  text "Top Layer - Bottom Layer" at 6600.13,3009.42 h60
  text "2" at 4997.27,2885.1 h60
  text "40.16mil (1.020mm)" at 5329.27,2885.1 h60
  text "PTH" at 5965.83,2885.1 h60
  text "Round" at 6224.97,2885.1 h60
  text "Top Layer - Bottom Layer" at 6600.13,2885.1 h60
  text "7" at 4997.27,2760.78 h60
  text "63.00mil (1.600mm)" at 5329.27,2760.78 h60
  text "PTH" at 5965.83,2760.78 h60
  text "Round" at 6224.97,2760.78 h60
  text "Top Layer - Bottom Layer" at 6600.13,2760.78 h60
  text "8" at 4997.27,2636.46 h60
  text "66.93mil (1.700mm)" at 5329.27,2636.46 h60
  text "PTH" at 5965.83,2636.46 h60
  text "Round" at 6224.97,2636.46 h60
  text "Top Layer - Bottom Layer" at 6600.13,2636.46 h60
  text "4" at 4997.27,2512.14 h60
  text "70.00mil (1.778mm)" at 5329.27,2512.14 h60
  text "PTH" at 5965.83,2512.14 h60
  text "Round" at 6224.97,2512.14 h60
  text "Top Layer - Bottom Layer" at 6600.13,2512.14 h60
  text "4" at 4997.27,2387.82 h60
  text "125.00mil (3.175mm)" at 5329.27,2387.82 h60
  text "PTH" at 5965.83,2387.82 h60
  text "Round" at 6224.97,2387.82 h60
  text "Top Layer - Bottom Layer" at 6600.13,2387.82 h60
  text "4" at 4997.27,2263.5 h60
  text "125.98mil (3.200mm)" at 5329.27,2263.5 h60
  text "PTH" at 5965.83,2263.5 h60
  text "Round" at 6224.97,2263.5 h60
  text "Top Layer - Bottom Layer" at 6600.13,2263.5 h60
  text "643 Total" at 4997.27,2139.18 h60
  text ".Layer_Name" at 577,-858.49 h30
M17 Embedded Cavity:
  text ".Layer_Name" at 577,-858.49 h30
M18 Embedded Assembly:
  text ".Layer_Name" at 577,-858.49 h30
M19 Embedded Keepout:
  text ".Layer_Name" at 577,-858.49 h30

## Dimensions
0,-400 to 1000,-400 on M2 Board Dimensions
0,0 to 0,3937.01 on M2 Board Dimensions
0,0 to 3937.01,0 on M2 Board Dimensions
